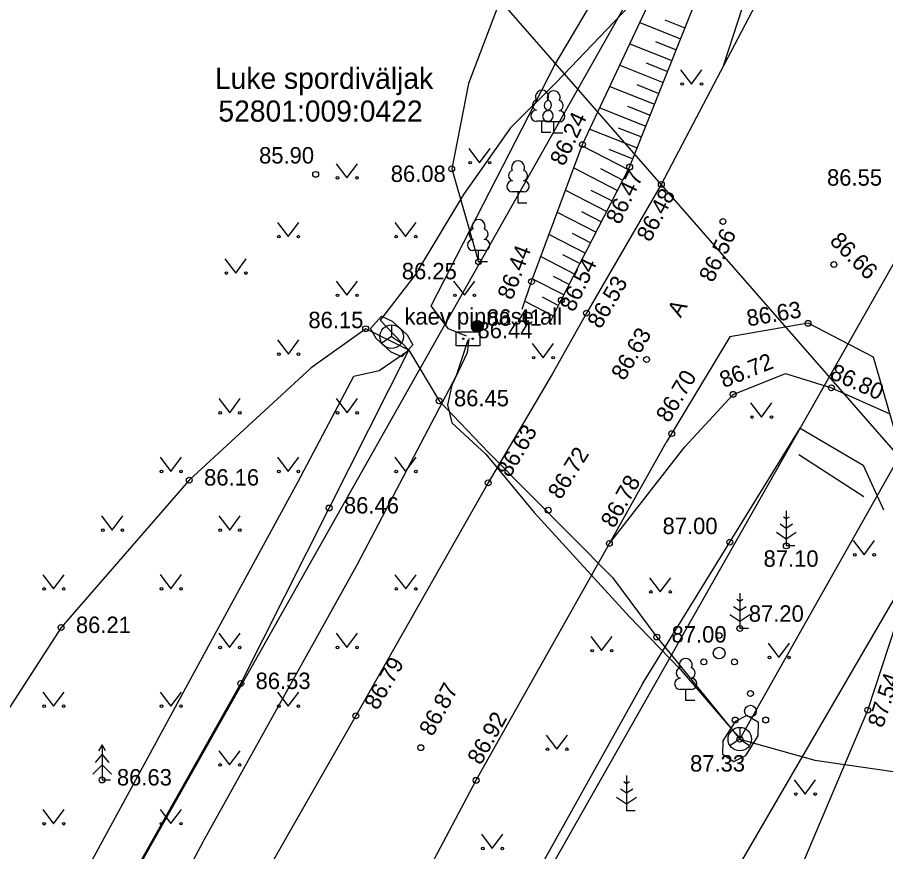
# Model space of a CAD drawing. Extents: x 648748 to 649126, y 6457789 to 6458252.
# Drawn here: x 648821.51 to 648858.5, y 6458054.26 to 6458089.78 of the extents above; entities that cross this region are included whole.
import ezdxf

# ---------------------------------------------------------------- set-up
doc = ezdxf.new("R2010")
doc.units = 0
for name, color, linetype in [('HALJASTUS', 7, 'Continuous'), ('KORGUS-EH2000', 7, 'Continuous'), ('KTRASS', 7, 'Continuous'), ('MPOHULIIN', 7, 'Continuous'), ('PIIR', 7, 'Continuous'), ('PUU', 7, 'Continuous'), ('RAJATIS', 7, 'Continuous'), ('RELJEEF', 7, 'Continuous'), ('SIKAEV', 7, 'Continuous'), ('SIRAJATIS', 7, 'Continuous'), ('SITRASS', 7, 'Continuous'), ('TEE', 7, 'Continuous')]:
    doc.layers.add(name, color=color, linetype=linetype)

msp = doc.modelspace()

# ---------------------------------------------------------------- linework, layer by layer
at = {"layer": 'HALJASTUS'}
for p, q in [((648849.769, 6458087.552), (648850.233, 6458086.945)), ((648850.233, 6458086.945), (648850.678, 6458087.552)), ((648840.741, 6458084.201), (648841.205, 6458083.594)), ((648841.205, 6458083.594), (648841.65, 6458084.201)), ((648835.091, 6458083.553), (648835.555, 6458082.947)), ((648835.555, 6458082.947), (648836, 6458083.553)), ((648832.591, 6458081.053), (648833.055, 6458080.447)), ((648833.055, 6458080.447), (648833.5, 6458081.053)), ((648837.591, 6458081.053), (648838.055, 6458080.447)), ((648838.055, 6458080.447), (648838.5, 6458081.053)), ((648830.353, 6458079.501), (648830.816, 6458078.894)), ((648830.816, 6458078.894), (648831.262, 6458079.501)), ((648835.092, 6458078.553), (648835.555, 6458077.947)), ((648835.555, 6458077.947), (648836.001, 6458078.553)), ((648840.092, 6458078.553), (648840.555, 6458077.947)), ((648840.555, 6458077.947), (648841.001, 6458078.553)), ((648832.593, 6458076.05), (648833.057, 6458075.443)), ((648833.057, 6458075.443), (648833.502, 6458076.05)), ((648843.447, 6458075.896), (648843.91, 6458075.29)), ((648843.91, 6458075.29), (648844.356, 6458075.896)), ((648830.093, 6458073.55), (648830.557, 6458072.943)), ((648830.557, 6458072.943), (648831.002, 6458073.55)), ((648835.093, 6458073.55), (648835.557, 6458072.943)), ((648835.557, 6458072.943), (648836.002, 6458073.55)), ((648852.75, 6458073.368), (648853.213, 6458072.762)), ((648853.213, 6458072.762), (648853.659, 6458073.368)), ((648857.569, 6458069.37), (648854.804, 6458071.157)), ((648827.592, 6458071.053), (648828.055, 6458070.447)), ((648828.055, 6458070.447), (648828.501, 6458071.053)), ((648832.592, 6458071.053), (648833.055, 6458070.447)), ((648833.055, 6458070.447), (648833.501, 6458071.053)), ((648837.592, 6458071.053), (648838.055, 6458070.447)), ((648838.055, 6458070.447), (648838.501, 6458071.053)), ((648825.093, 6458068.55), (648825.557, 6458067.943)), ((648825.557, 6458067.943), (648826.002, 6458068.55)), ((648830.093, 6458068.55), (648830.557, 6458067.943)), ((648830.557, 6458067.943), (648831.002, 6458068.55)), ((648857.124, 6458067.505), (648857.588, 6458066.898)), ((648857.588, 6458066.898), (648858.033, 6458067.505)), ((648822.593, 6458066.05), (648823.057, 6458065.443)), ((648823.057, 6458065.443), (648823.502, 6458066.05)), ((648827.592, 6458066.053), (648828.055, 6458065.447)), ((648828.055, 6458065.447), (648828.501, 6458066.053)), ((648837.593, 6458066.05), (648838.057, 6458065.443)), ((648838.057, 6458065.443), (648838.502, 6458066.05)), ((648848.439, 6458065.922), (648848.902, 6458065.315)), ((648848.902, 6458065.315), (648849.348, 6458065.922)), ((648830.092, 6458063.553), (648830.555, 6458062.947)), ((648830.555, 6458062.947), (648831.001, 6458063.553)), ((648835.092, 6458063.553), (648835.555, 6458062.947)), ((648835.555, 6458062.947), (648836.001, 6458063.553)), ((648845.939, 6458063.422), (648846.402, 6458062.815)), ((648846.402, 6458062.815), (648846.848, 6458063.422)), ((648853.494, 6458063.131), (648853.958, 6458062.524)), ((648853.958, 6458062.524), (648854.403, 6458063.131)), ((648822.592, 6458061.053), (648823.055, 6458060.447)), ((648823.055, 6458060.447), (648823.501, 6458061.053)), ((648827.592, 6458061.053), (648828.055, 6458060.447)), ((648828.055, 6458060.447), (648828.501, 6458061.053)), ((648832.592, 6458061.053), (648833.055, 6458060.447)), ((648833.055, 6458060.447), (648833.501, 6458061.053)), ((648844.034, 6458059.22), (648844.498, 6458058.614)), ((648844.498, 6458058.614), (648844.943, 6458059.22)), ((648830.092, 6458058.553), (648830.555, 6458057.947)), ((648830.555, 6458057.947), (648831.001, 6458058.553)), ((648854.611, 6458057.314), (648855.075, 6458056.707)), ((648855.075, 6458056.707), (648855.52, 6458057.314)), ((648822.593, 6458056.049), (648823.057, 6458055.443)), ((648823.057, 6458055.443), (648823.502, 6458056.049)), ((648827.592, 6458056.053), (648828.055, 6458055.447)), ((648828.055, 6458055.447), (648828.501, 6458056.053)), ((648841.282, 6458054.995), (648841.745, 6458054.388)), ((648841.745, 6458054.388), (648842.191, 6458054.995))]:
    msp.add_line(p, q, dxfattribs=at)
for points in [[(648846.409, 6458109.758), (648846.103, 6458107.557), (648844.069, 6458095.756), (648840.734, 6458086.96), (648840.017, 6458083.336), (648841.163, 6458079.375)], [(648848.144, 6458061.397), (648851.867, 6458067.436), (648854.862, 6458072.295), (648857.543, 6458070.711), (648858.408, 6458068.811)], [(648848.144, 6458061.397), (648843.695, 6458053.431), (648837.782, 6458042.965), (648828.866, 6458027.575)]]:
    msp.add_lwpolyline(points, dxfattribs=at)
for centre in [(648849.832, 6458086.945), (648850.661, 6458086.945), (648840.804, 6458083.594), (648841.633, 6458083.594), (648835.154, 6458082.947), (648835.983, 6458082.947), (648832.654, 6458080.447), (648833.483, 6458080.447), (648837.654, 6458080.447), (648838.483, 6458080.447), (648830.415, 6458078.894), (648831.244, 6458078.894), (648835.154, 6458077.947), (648835.983, 6458077.947), (648840.154, 6458077.947), (648840.983, 6458077.947), (648832.656, 6458075.443), (648833.485, 6458075.443), (648843.509, 6458075.29), (648844.338, 6458075.29), (648830.156, 6458072.943), (648830.985, 6458072.943), (648835.156, 6458072.943), (648835.985, 6458072.943), (648852.812, 6458072.762), (648853.641, 6458072.762), (648827.654, 6458070.447), (648828.483, 6458070.447), (648832.654, 6458070.447), (648833.483, 6458070.447), (648837.654, 6458070.447), (648838.483, 6458070.447), (648825.156, 6458067.943), (648825.985, 6458067.943), (648830.156, 6458067.943), (648830.985, 6458067.943), (648857.187, 6458066.898), (648858.016, 6458066.898), (648822.656, 6458065.443), (648823.485, 6458065.443), (648827.654, 6458065.447), (648828.483, 6458065.447), (648837.656, 6458065.443), (648838.485, 6458065.443), (648848.501, 6458065.315), (648849.33, 6458065.315), (648830.154, 6458062.947), (648830.983, 6458062.947), (648835.154, 6458062.947), (648835.983, 6458062.947), (648846.001, 6458062.815), (648846.83, 6458062.815), (648853.557, 6458062.524), (648854.386, 6458062.524), (648822.654, 6458060.447), (648823.483, 6458060.447), (648827.654, 6458060.447), (648828.483, 6458060.447), (648832.654, 6458060.447), (648833.483, 6458060.447), (648844.097, 6458058.614), (648844.926, 6458058.614), (648830.154, 6458057.947), (648830.983, 6458057.947), (648854.674, 6458056.707), (648855.503, 6458056.707), (648822.656, 6458055.443), (648823.485, 6458055.443), (648827.654, 6458055.447), (648828.483, 6458055.447), (648841.344, 6458054.388), (648842.173, 6458054.388)]:
    msp.add_circle(centre, 0.055, dxfattribs=at)
at = {"layer": 'KORGUS-EH2000'}
for centre in [(648845.59, 6458084.371), (648840.017, 6458083.336), (648847.597, 6458083.411), (648834.222, 6458083.097), (648848.947, 6458082.671), (648851.573, 6458081.092), (648841.163, 6458079.375), (648856.3, 6458079.259), (648843.42, 6458078.532), (648844.687, 6458077.74), (648845.759, 6458077.188), (648836.351, 6458076.524), (648855.198, 6458076.755), (648848.317, 6458075.212), (648856.194, 6458074.004), (648852.009, 6458073.729), (648839.481, 6458073.453), (648849.39, 6458072.057), (648828.836, 6458070.077), (648841.568, 6458069.96), (648834.793, 6458068.888), (648844.129, 6458068.793), (648846.734, 6458067.377), (648851.867, 6458067.436), (648854.273, 6458067.273), (648823.373, 6458063.799), (648852.296, 6458063.758), (648848.753, 6458063.394), (648831.029, 6458061.413), (648857.741, 6458060.282), (648835.932, 6458060.036), (648852.29, 6458059.046), (648838.699, 6458058.682), (648825.121, 6458057.305), (648841.055, 6458057.292)]:
    msp.add_circle(centre, 0.125, dxfattribs=at)
at = {"layer": 'KTRASS'}
msp.add_line((648859.239, 6458070.903), (648842.056, 6458090.562), dxfattribs=at)
at = {"layer": 'MPOHULIIN'}
msp.add_line((648863.647, 6458073.263), (648847.655, 6458045.759), dxfattribs=at)
at = {"layer": 'PIIR'}
for p, q in [((648868.92, 6458128.41), (648793.25, 6457994.41)), ((648796.52, 6457969.47), (648863.67, 6458087.81))]:
    msp.add_line(p, q, dxfattribs=at)
at = {"layer": 'PUU'}
for p, q in [((648844.103, 6458085.356), (648843.623, 6458085.356)), ((648843.863, 6458084.881), (648843.863, 6458085.356)), ((648844.604, 6458085.33), (648844.124, 6458085.33)), ((648844.364, 6458084.855), (648844.364, 6458085.33)), ((648844.243, 6458084.881), (648843.863, 6458084.881)), ((648844.744, 6458084.855), (648844.364, 6458084.855)), ((648843.083, 6458082.35), (648842.603, 6458082.35)), ((648842.843, 6458081.875), (648842.843, 6458082.35)), ((648843.223, 6458081.875), (648842.843, 6458081.875)), ((648841.403, 6458079.85), (648840.923, 6458079.85)), ((648841.163, 6458079.375), (648841.163, 6458079.85)), ((648841.543, 6458079.375), (648841.163, 6458079.375)), ((648854.273, 6458068.773), (648854.273, 6458067.273)), ((648854.273, 6458068.023), (648854.007, 6458068.201)), ((648854.273, 6458068.423), (648854.149, 6458068.506)), ((648854.398, 6458068.506), (648854.273, 6458068.423)), ((648854.54, 6458068.201), (648854.273, 6458068.023)), ((648853.849, 6458067.863), (648854.273, 6458067.58)), ((648854.273, 6458067.58), (648854.698, 6458067.863)), ((648854.633, 6458067.273), (648854.273, 6458067.273)), ((648852.296, 6458065.258), (648852.296, 6458063.758)), ((648852.296, 6458064.907), (648852.171, 6458064.99)), ((648852.42, 6458064.99), (648852.296, 6458064.907)), ((648852.296, 6458064.508), (648852.029, 6458064.685)), ((648852.562, 6458064.685), (648852.296, 6458064.508)), ((648851.871, 6458064.347), (648852.296, 6458064.064)), ((648852.296, 6458064.064), (648852.72, 6458064.347)), ((648852.656, 6458063.758), (648852.296, 6458063.758)), ((648850.228, 6458061.163), (648849.748, 6458061.163)), ((648849.988, 6458060.688), (648849.988, 6458061.163)), ((648850.368, 6458060.688), (648849.988, 6458060.688)), ((648825.121, 6458058.805), (648824.971, 6458058.555)), ((648825.271, 6458058.555), (648825.121, 6458058.805)), ((648825.121, 6458058.805), (648825.121, 6458057.305)), ((648825.121, 6458058.405), (648824.821, 6458058.055)), ((648825.421, 6458058.055), (648825.121, 6458058.405)), ((648825.121, 6458057.955), (648824.721, 6458057.555)), ((648825.521, 6458057.555), (648825.121, 6458057.955)), ((648847.467, 6458057.491), (648847.467, 6458055.991)), ((648825.481, 6458057.305), (648825.121, 6458057.305)), ((648847.467, 6458057.141), (648847.343, 6458057.224)), ((648847.592, 6458057.224), (648847.467, 6458057.141)), ((648847.467, 6458056.741), (648847.201, 6458056.918)), ((648847.734, 6458056.918), (648847.467, 6458056.741)), ((648847.043, 6458056.58), (648847.467, 6458056.297)), ((648847.467, 6458056.297), (648847.892, 6458056.58)), ((648847.827, 6458055.991), (648847.467, 6458055.991))]:
    msp.add_line(p, q, dxfattribs=at)
for centre, radius in [((648851.412, 6458063.459), 0.125), ((648851.412, 6458062.709), 0.25), ((648850.762, 6458062.334), 0.125), ((648852.062, 6458062.334), 0.125), ((648852.743, 6458060.986), 0.125), ((648852.743, 6458060.236), 0.25), ((648852.093, 6458059.861), 0.125), ((648853.393, 6458059.861), 0.125)]:
    msp.add_circle(centre, radius, dxfattribs=at)
for centre, radius, start, end in [((648843.863, 6458086.401), 0.277, 332.58, 207.42), ((648844.364, 6458086.376), 0.277, 332.58, 207.42), ((648843.693, 6458086.053), 0.233, 109.022, 253.142), ((648844.033, 6458086.053), 0.233, 286.851, 70.986), ((648844.194, 6458086.028), 0.233, 109.022, 253.142), ((648844.534, 6458086.028), 0.233, 286.851, 70.986), ((648843.626, 6458085.593), 0.238, 90.002, 269.395), ((648844.127, 6458085.568), 0.238, 90.002, 269.395), ((648844.101, 6458085.593), 0.238, 270.605, 89.998), ((648844.602, 6458085.568), 0.238, 270.605, 89.998), ((648842.843, 6458083.395), 0.277, 332.58, 207.42), ((648842.673, 6458083.048), 0.233, 109.022, 253.142), ((648843.013, 6458083.048), 0.233, 286.851, 70.986), ((648842.606, 6458082.588), 0.238, 90.002, 269.395), ((648843.081, 6458082.588), 0.238, 270.605, 89.998), ((648841.163, 6458080.895), 0.277, 332.58, 207.42), ((648840.993, 6458080.548), 0.233, 109.022, 253.142), ((648841.333, 6458080.548), 0.233, 286.851, 70.986), ((648840.926, 6458080.088), 0.238, 90.002, 269.395), ((648841.401, 6458080.088), 0.238, 270.605, 89.998), ((648849.988, 6458062.208), 0.277, 332.58, 207.42), ((648849.818, 6458061.861), 0.233, 109.022, 253.142), ((648850.158, 6458061.861), 0.233, 286.851, 70.986), ((648849.751, 6458061.401), 0.238, 90.002, 269.395), ((648850.226, 6458061.401), 0.238, 270.605, 89.998)]:
    msp.add_arc(centre, radius, start, end, dxfattribs=at)
at = {"layer": 'RAJATIS'}
for radius in [0.25, 0.225, 0.2, 0.175, 0.15, 0.125, 0.1, 0.075, 0.05, 0.025]:
    msp.add_circle((648841.107, 6458076.628), radius, dxfattribs=at)
at = {"layer": 'RELJEEF'}
for p, q in [((648849.098, 6458089.676), (648849.955, 6458089.335)), ((648848.029, 6458089.563), (648849.77, 6458088.871)), ((648847.603, 6458088.657), (648849.4, 6458087.941)), ((648848.7, 6458088.758), (648849.585, 6458088.406)), ((648847.177, 6458087.75), (648849.03, 6458087.012)), ((648848.303, 6458087.84), (648849.215, 6458087.477)), ((648846.751, 6458086.843), (648848.661, 6458086.083)), ((648847.905, 6458086.922), (648848.846, 6458086.548)), ((648846.325, 6458085.936), (648848.291, 6458085.154)), ((648847.507, 6458086.004), (648848.476, 6458085.619)), ((648845.899, 6458085.029), (648847.921, 6458084.225)), ((648847.109, 6458085.086), (648848.106, 6458084.689)), ((648845.569, 6458084.313), (648847.541, 6458083.301)), ((648846.712, 6458084.168), (648847.737, 6458083.76)), ((648845.218, 6458083.369), (648847.084, 6458082.411)), ((648846.353, 6458083.348), (648847.313, 6458082.856)), ((648844.867, 6458082.425), (648846.628, 6458081.521)), ((648845.949, 6458082.431), (648846.856, 6458081.966)), ((648844.516, 6458081.481), (648846.171, 6458080.632)), ((648845.545, 6458081.515), (648846.399, 6458081.076)), ((648844.165, 6458080.537), (648845.715, 6458079.742)), ((648845.142, 6458080.598), (648845.943, 6458080.187)), ((648844.738, 6458079.681), (648845.486, 6458079.297)), ((648843.814, 6458079.593), (648845.258, 6458078.852)), ((648843.463, 6458078.649), (648844.801, 6458077.963)), ((648844.334, 6458078.764), (648845.03, 6458078.407)), ((648843.877, 6458077.875), (648844.573, 6458077.518)), ((648843.134, 6458077.694), (648844.345, 6458077.073))]:
    msp.add_line(p, q, dxfattribs=at)
for points in [[(648843.02, 6458077.359), (648843.42, 6458078.532), (648845.59, 6458084.371), (648850.065, 6458093.899), (648854.008, 6458102.777), (648855.882, 6458106.866), (648857.274, 6458110.27), (648859.944, 6458115.461), (648864.155, 6458122.302), (648866.203, 6458125.31), (648868.207, 6458128.087), (648874.51, 6458135.307), (648877.92, 6458139.306), (648882.178, 6458146.884)], [(648844.206, 6458076.8), (648844.687, 6458077.74), (648847.597, 6458083.411), (648851.411, 6458092.995), (648855.57, 6458101.941), (648857.624, 6458105.762), (648858.713, 6458108.175), (648859.587, 6458110.038), (648862.771, 6458115.697), (648866.339, 6458121.712), (648870.456, 6458126.824), (648876.009, 6458134.263), (648879.482, 6458138.641), (648881.386, 6458142.032), (648883.388, 6458145.778), (648883.683, 6458146.633)]]:
    msp.add_lwpolyline(points, dxfattribs=at)
at = {"layer": 'SIKAEV'}
for p, q in [((648837.457, 6458076.688), (648837.457, 6458076.188)), ((648837.457, 6458076.188), (648837.042, 6458075.913)), ((648837.457, 6458076.188), (648837.872, 6458075.913)), ((648852.29, 6458059.546), (648852.29, 6458059.046)), ((648852.29, 6458059.046), (648851.875, 6458058.771)), ((648852.29, 6458059.046), (648852.705, 6458058.771))]:
    msp.add_line(p, q, dxfattribs=at)
for points in [[(648838.358, 6458075.84), (648837.886, 6458075.323), (648837.438, 6458075.528), (648836.802, 6458076.108), (648836.556, 6458076.536), (648837.028, 6458077.053), (648837.476, 6458076.847), (648838.112, 6458076.267), (648838.358, 6458075.84)], [(648852.549, 6458058.351), (648853.072, 6458059.18), (648853.088, 6458059.749), (648852.597, 6458060.059), (648852.091, 6458059.799), (648851.568, 6458058.97), (648851.552, 6458058.401), (648852.043, 6458058.091), (648852.549, 6458058.351)]]:
    msp.add_lwpolyline(points, dxfattribs=at)
for centre in [(648837.457, 6458076.188), (648852.29, 6458059.046)]:
    msp.add_circle(centre, 0.5, dxfattribs=at)
at = {"layer": 'SIRAJATIS'}
msp.add_lwpolyline([(648840.208, 6458076.395), (648841.208, 6458076.395), (648841.208, 6458075.795), (648840.208, 6458075.795)], close=True, dxfattribs=at)
for centre, radius in [((648840.508, 6458076.095), 0.0304), ((648840.508, 6458076.095), 0.029), ((648840.508, 6458076.095), 0.0277), ((648840.508, 6458076.095), 0.0263), ((648840.508, 6458076.095), 0.0249), ((648840.508, 6458076.095), 0.0236), ((648840.508, 6458076.095), 0.0222), ((648840.508, 6458076.095), 0.0209), ((648840.508, 6458076.095), 0.0195), ((648840.508, 6458076.095), 0.0181), ((648840.508, 6458076.095), 0.0168), ((648840.508, 6458076.095), 0.0154), ((648840.508, 6458076.095), 0.014), ((648840.508, 6458076.095), 0.0127), ((648840.508, 6458076.095), 0.0113), ((648840.508, 6458076.095), 0.00996), ((648840.508, 6458076.095), 0.0086), ((648840.508, 6458076.095), 0.00724), ((648840.508, 6458076.095), 0.00587), ((648840.508, 6458076.095), 0.00451), ((648840.508, 6458076.095), 0.00315), ((648840.508, 6458076.095), 0.00179), ((648840.508, 6458076.095), 0.000426), ((648840.908, 6458076.095), 0.0304), ((648840.908, 6458076.095), 0.029), ((648840.908, 6458076.095), 0.0277), ((648840.908, 6458076.095), 0.0263), ((648840.908, 6458076.095), 0.0249), ((648840.908, 6458076.095), 0.0236), ((648840.908, 6458076.095), 0.0222), ((648840.908, 6458076.095), 0.0209), ((648840.908, 6458076.095), 0.0195), ((648840.908, 6458076.095), 0.0181), ((648840.908, 6458076.095), 0.0168), ((648840.908, 6458076.095), 0.0154), ((648840.908, 6458076.095), 0.014), ((648840.908, 6458076.095), 0.0127), ((648840.908, 6458076.095), 0.0113), ((648840.908, 6458076.095), 0.00996), ((648840.908, 6458076.095), 0.0086), ((648840.908, 6458076.095), 0.00724), ((648840.908, 6458076.095), 0.00587), ((648840.908, 6458076.095), 0.00451), ((648840.908, 6458076.095), 0.00315), ((648840.908, 6458076.095), 0.00179), ((648840.908, 6458076.095), 0.000426)]:
    msp.add_circle(centre, radius, dxfattribs=at)
at = {"layer": 'SITRASS'}
msp.add_line((648852.29, 6458059.046), (648876.861, 6458102.566), dxfattribs=at)
for points in [[(648896.343, 6458186.017), (648897.439, 6458185.494), (648891.994, 6458176.157), (648887.134, 6458166.562), (648880.865, 6458155.928), (648874.577, 6458143.726), (648870.442, 6458134.893), (648860.973, 6458120.207), (648854.483, 6458107.787), (648851.762, 6458098.853), (648850.917, 6458095.378), (648847.878, 6458090.581), (648844.467, 6458087.013), (648842.522, 6458085.072), (648840.521, 6458082.239)], [(648840.642, 6458076.21), (648839.879, 6458076.526), (648839.144, 6458077.498), (648844.394, 6458087.729), (648849.387, 6458096.156), (648854.312, 6458104.237), (648857.262, 6458110.389), (648861.217, 6458117.552), (648863.683, 6458121.25), (648863.975, 6458121.708)], [(648840.521, 6458082.239), (648838.462, 6458078.82), (648836.968, 6458076.883), (648838.183, 6458075.605)], [(648838.183, 6458075.605), (648836.351, 6458076.524), (648834.032, 6458074.854), (648828.836, 6458070.077), (648823.373, 6458063.799), (648815.041, 6458050.907), (648808.674, 6458038.587), (648805.571, 6458032.708), (648798.852, 6458019.324), (648793.359, 6458009.366), (648788.414, 6457998.68), (648785.353, 6457991.074), (648783.686, 6457988.513), (648778.988, 6457980.101), (648777.337, 6457977.723), (648774.295, 6457973.649), (648772.508, 6457971.285), (648769.936, 6457967.433)], [(648840.698, 6458076.036), (648840.206, 6458074.518), (648835.992, 6458066.48), (648829.455, 6458054.737), (648823.386, 6458043.337), (648816.202, 6458031.074), (648810.097, 6458020.648), (648803.233, 6458008.294), (648797.369, 6457997.813), (648791.835, 6457987.5), (648788.847, 6457982.267), (648783.409, 6457971.182), (648777.403, 6457959.148), (648772.285, 6457949.688)], [(648840.745, 6458076.11), (648840.68, 6458075.494), (648840.024, 6458074.127), (648839.832, 6458073.28), (648840.019, 6458072.522)], [(648771.558, 6457962.366), (648777.323, 6457971.169), (648780.294, 6457977.006), (648783.881, 6457983.462), (648786.386, 6457988.106), (648790.088, 6457993.164), (648795.127, 6458001.6), (648799.018, 6458008.179), (648807.603, 6458023.185), (648816.805, 6458039.666), (648823.715, 6458052.086), (648829.839, 6458063.342), (648833.461, 6458069.995), (648835.841, 6458074.502), (648836.926, 6458074.748), (648838.183, 6458075.605)], [(648772.534, 6457959.145), (648778.305, 6457968.987), (648782.296, 6457976.466), (648786.131, 6457983.091), (648788.533, 6457986.692), (648790.268, 6457990.62), (648793.726, 6457995.075), (648800.38, 6458006.925), (648808.978, 6458022.031), (648818.066, 6458038.429), (648824.931, 6458050.586), (648831.029, 6458061.413), (648834.793, 6458068.888), (648838.183, 6458075.605), (648839.481, 6458073.453), (648841.568, 6458071.264), (648846.872, 6458065.923), (648848.753, 6458063.394)], [(648840.019, 6458072.522), (648841.465, 6458071.176), (648843.535, 6458068.7), (648847.588, 6458064.248), (648849.75, 6458062.02), (648851.911, 6458059.514), (648852.32, 6458059.075)], [(648848.753, 6458063.394), (648852.29, 6458059.046)], [(648852.29, 6458059.046), (648855.487, 6458058.152), (648859.118, 6458057.625), (648862.515, 6458056.366), (648866.295, 6458055.555)]]:
    msp.add_lwpolyline(points, dxfattribs=at)
at = {"layer": 'TEE'}
msp.add_line((648846.734, 6458067.377), (648849.948, 6458071.491), dxfattribs=at)
for points in [[(648886.897, 6458149.241), (648880.501, 6458138.274), (648877.651, 6458133.428), (648873.007, 6458125.579), (648869.584, 6458119.515), (648862.268, 6458107.116), (648858.84, 6458100.574), (648853.992, 6458092.302), (648848.947, 6458082.671), (648845.759, 6458077.188), (648844.3, 6458074.59)], [(648861.563, 6458110.828), (648860.521, 6458108.202), (648859.649, 6458106.006), (648857.599, 6458101.033), (648853.187, 6458092.651), (648851.603, 6458087.741)], [(648809.885, 6457960.062), (648810.233, 6457960.629), (648815.43, 6457971.592), (648817.584, 6457976.36), (648820.136, 6457981.696), (648823.114, 6457989.321), (648828.108, 6457999.323), (648833.019, 6458009.341), (648838.119, 6458018.946), (648839.695, 6458023.154), (648843.481, 6458029.976), (648843.97, 6458031.062), (648845.559, 6458034.741), (648849.963, 6458043.601), (648853.751, 6458050.875), (648857.741, 6458060.282), (648859.244, 6458064.865), (648859.613, 6458067.904), (648859.358, 6458070.552), (648857.99, 6458075.311), (648855.198, 6458076.755), (648851.865, 6458076.18), (648849.159, 6458071.672)], [(648844.3, 6458074.59), (648841.568, 6458069.96), (648835.932, 6458060.036), (648830.008, 6458049.677), (648824.317, 6458039.384), (648818.356, 6458028.958), (648812.613, 6458018.629), (648806.656, 6458008.281), (648800.566, 6457997.472), (648794.382, 6457986.281), (648790.808, 6457979.567), (648784.572, 6457968.758), (648779.694, 6457960.62), (648774.527, 6457951.036)], [(648849.948, 6458071.491), (648852.009, 6458073.729), (648854.234, 6458074.624), (648856.194, 6458074.004), (648858.685, 6458072.894)], [(648795.708, 6457976.678), (648799.747, 6457983.584), (648805.652, 6457994.165), (648811.974, 6458005.315), (648817.667, 6458015.456), (648823.8, 6458025.997), (648829.771, 6458036.425), (648835.506, 6458046.826), (648841.055, 6458057.292), (648846.734, 6458067.377), (648849.159, 6458071.672)]]:
    msp.add_lwpolyline(points, dxfattribs=at)

# ---------------------------------------------------------------- texts
at = {"layer": 'KORGUS-EH2000'}
for s, rotation, p in [('86.24', 64.8429, (648844.799, 6458083.411)), ('86.47', 64.2993, (648847.178, 6458080.924)), ('86.48', 62.3499, (648848.475, 6458080.179)), ('86.56', 64.5367, (648851.15, 6458078.455)), ('86.66', 315, (648856.082, 6458080.218)), ('86.44', 69.6062, (648842.595, 6458077.711)), ('86.54', 64.7671, (648845.224, 6458077.199)), ('86.53', 59.8267, (648846.357, 6458076.478)), ('86.63', 9.7932, (648852.646, 6458076.618)), ('86.63', 59.8221, (648847.371, 6458074.274)), ('86.72', 21.9305, (648851.608, 6458073.988)), ('86.80', 335.9604, (648856.078, 6458074.421)), ('86.70', 59.0219, (648849.271, 6458072.481)), (' 86.63', 59.4608, (648842.36, 6458069.925)), (' 86.72', 58.2454, (648844.523, 6458068.987)), (' 86.78', 60.5502, (648846.804, 6458067.765)), (' 86.79', 60.4072, (648836.725, 6458060.014)), (' 86.87', 61.7634, (648839.081, 6458058.9)), ('87.54', 71.8381, (648858.386, 6458059.492)), (' 86.92', 60.6171, (648841.124, 6458057.68))]:
    msp.add_text(s, height=0.7, rotation=rotation, dxfattribs=at).set_placement(p)
for s, p in [('85.90', (648831.81, 6458083.56)), ('86.08', (648837.42, 6458082.775)), ('86.55', (648856.008, 6458082.615)), ('86.25', (648837.891, 6458078.628)), (' 86.15', (648833.651, 6458076.547)), ('86.41', (648841.514, 6458076.651)), ('86.44', (648841.115, 6458076.118)), (' 86.45', (648839.853, 6458073.22)), (' 86.16', (648829.208, 6458069.844)), (' 86.46', (648835.165, 6458068.655)), ('87.00', (648849.001, 6458067.777)), ('87.10', (648853.303, 6458066.386)), ('87.20', (648852.674, 6458064.045)), (' 86.21', (648823.745, 6458063.566)), (' 87.00', (648849.125, 6458063.161)), (' 86.53', (648831.401, 6458061.18)), ('87.33', (648850.172, 6458057.665)), (' 86.63', (648825.493, 6458057.072))]:
    msp.add_text(s, height=0.7, dxfattribs=at).set_placement(p)
at = {"layer": 'PIIR'}
for s, p in [('Luke spordiväljak', (648829.928, 6458086.739)), ('52801:009:0422', (648830.076, 6458085.343))]:
    msp.add_text(s, height=0.9, rotation=360, dxfattribs=at).set_placement(p)
at = {"layer": 'SIKAEV'}
msp.add_text('kaev pinnase all', height=0.7, dxfattribs=at).set_placement((648838.004, 6458076.699))
at = {"layer": 'TEE'}
msp.add_text('A', height=0.7, rotation=60.2687, dxfattribs=at).set_placement((648849.77, 6458076.958))

doc.saveas('drawing.dxf')
